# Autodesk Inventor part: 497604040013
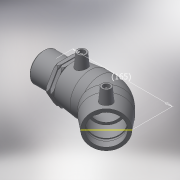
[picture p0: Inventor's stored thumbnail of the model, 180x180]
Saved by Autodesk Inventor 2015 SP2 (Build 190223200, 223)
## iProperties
Created: 2017-06
Part Number: 497604040013
Material: Generic
Description: PLASSON PE MALE TRANSITION 45° ELBOW 40-1.1/4"
Document SubType Name: Modeling
Designer: KIM
Mass: 55.0731 g
Surface Area: 148.067 cm^2
Volume: 55.0731 cm^3
Density: 1 g/cm^3
Appearance: Default
Author: KIM
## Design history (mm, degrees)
derived "497604.ipt"
feature "Solid1::497604.ipt"
tag "TaggingFeature1"
body "Solid1"
other parameters: "d2" = 56, "d4" = 26.5, "d5" = 50.4, "d8" = 168 deg, "d10" = 16.8, "d11" = 5.6, "d29" = 47, "d30" = 15, "d31" = 37.1, "d34" = 5 deg, "d41" = 4, "d42" = 14, "d43" = 0, "d50" = 34, "d51" = 16.8, "d52" = 41.9, "d54" = 135 deg, "d86" = 25.2, "d87" = 135 deg, "d88" = 106, "d90" = 33.6, "d91" = 0, "d92" = 42, "d93" = 0, "d101" = 3, "d102" = 0, "d107" = 0.1, "d109" = 41.91, "d110" = 42, "d111" = 10.5, "d112" = 56, "d113" = 29.337, "d114" = 37.8, "d116" = 1.68, "d122" = 0, "d123" = 2.0955, "d126" = 1.05, "d127" = 4.725, "d128" = 56, "d130" = 42, "L_" = 148, "L_2" = 42, "A_" = 47, "d_2" = 12, "L_1" = 42, "R_" = 41.91, "D_1" = 56, "d129" = 148
